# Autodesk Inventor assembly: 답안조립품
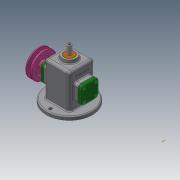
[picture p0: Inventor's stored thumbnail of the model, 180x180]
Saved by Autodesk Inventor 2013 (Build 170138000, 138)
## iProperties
Created: 2021-08
Part Number: 답안조립품
Document SubType Name: Assembly
Designer: kum
Author: kum
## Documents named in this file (16)
- C:\Users\kum\Desktop\710806V1023\답안조립품.iam
- C:\Users\kum\Desktop\710806V1023\본체.ipt
- C:\Users\kum\Desktop\710806V1023\V벨트풀리.ipt
- C:\Users\kum\Desktop\710806V1023\고정핀 1.2x8.ipt
- C:\Users\kum\Desktop\710806V1023\뒤커버.ipt
- C:\Users\kum\Desktop\710806V1023\링크.ipt
- C:\Users\kum\Desktop\710806V1023\멈춤나사 M3x8.ipt
- C:\Users\kum\Desktop\710806V1023\베어링 12x32x10.ipt
- C:\Users\kum\Desktop\710806V1023\볼트 M4.ipt
- C:\Users\kum\Desktop\710806V1023\부시.ipt
- C:\Users\kum\Desktop\710806V1023\슬라이드.ipt
- C:\Users\kum\Desktop\710806V1023\앞커버.ipt
- C:\Users\kum\Desktop\710806V1023\오일 실 12 25 7.ipt
- C:\Users\kum\Desktop\710806V1023\키 4x4x10.ipt
- C:\Users\kum\Desktop\710806V1023\편심축.ipt
- C:\Users\kum\Desktop\710806V1023\핀 5x18.ipt
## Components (3 placed, 3 different names)
1. V벨트풀리:1 — 플러쉬:2
2. 고정핀 1.2x8:1
3. 핀 5x18:1
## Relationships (1: Flush 1)
- 플러쉬:2 [Flush]: V벨트풀리:1
